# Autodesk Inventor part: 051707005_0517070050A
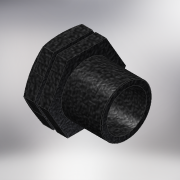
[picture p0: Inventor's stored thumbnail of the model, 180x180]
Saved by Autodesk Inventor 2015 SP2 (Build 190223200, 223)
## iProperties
Created: 2017-05
Part Number: 051707005_0517070050A
Material: Generic
Description: PLASSON PLUG 1/2"
Document SubType Name: Modeling
Designer: Кирилл
Density: 1 g/cm^3
Appearance: Black Cast
Author: Кирилл
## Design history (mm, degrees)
derived "051707.ipt"
feature "Solid1::051707.ipt"
tag "TaggingFeature1"
body "Solid1"
other parameters: "d1" = 20.955, "d2" = 27, "d3" = 16, "d5" = 16, "d6" = 4.14286, "d8" = 0.29, "d12" = 0, "d14" = 1.38095, "d15" = 29, "d16" = 1.65714, "d17" = 4.14286, "d19" = 0, "d21" = 2.2, "d29" = 0, "H_" = 29, "R_" = 20.955, "E_" = 27, "l_2" = 16, "d20" = 3.33333
